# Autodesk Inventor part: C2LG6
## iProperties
Shininess: 64.0
Length Units: 11272
Angle Units: 11279
Time Units: 11290
Mass Units: 11286
Length Display Precision: 3
Angle Display Precision: 2
Compacted: True
Part Number: C2LG6
Document SubType Name: Modeling
Created: 2003-12
Designer: Charles Bliss
Manufacturer: Standard
Standards Organization: Custom
Material: PVC-Piping
Density: 0.0
Volumn: 0.0
Area: 0.0
PropertySet Name: Model Information
Control State: 0
Master: False
Checked Out: False
Author: Charles Bliss
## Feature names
1. Extrusion1
